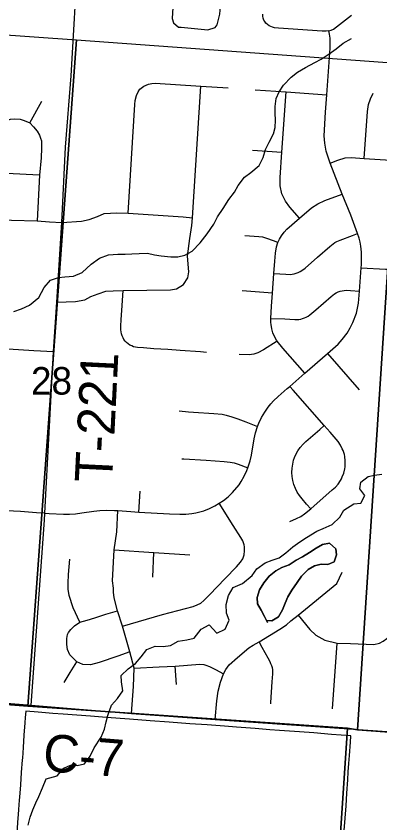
# Model space of a CAD drawing. Extents: x 0 to 34, y 0 to 26.1.
# Drawn here: x 26.1 to 26.652, y 15.919 to 17.147 of the extents above; entities that cross this region are included whole.
import ezdxf

# ---------------------------------------------------------------- set-up
doc = ezdxf.new("R2010")
doc.units = 0
for name, color, linetype in [('GM_X_County_Road', 7, 'Continuous'), ('GM_X_County_Road_Text', 7, 'Continuous'), ('GM_X_Minor_Lake', 7, 'Continuous'), ('GM_X_Minor_River', 7, 'Continuous'), ('GM_X_Section', 7, 'Continuous'), ('GM_X_Section_Text', 7, 'Continuous'), ('GM_X_Township_Road', 7, 'Continuous'), ('GM_X_Township_Road_Text', 7, 'Continuous'), ('SC_Scratch1', 7, 'Continuous')]:
    doc.layers.add(name, color=color, linetype=linetype)

msp = doc.modelspace()

# ---------------------------------------------------------------- linework, layer by layer
at = {"layer": 'GM_X_County_Road'}
msp.add_lwpolyline([(25.6593, 16.1329), (25.6738, 16.1311), (25.7938, 16.1231), (25.9933, 16.107), (26.0793, 16.1018), (26.1222, 16.0984), (26.2747, 16.0857), (26.4019, 16.0766), (26.714, 16.0547), (26.8597, 16.0424), (26.9166, 16.0392), (26.9722, 16.0347), (26.9948, 16.0336), (27.0202, 16.032), (27.0574, 16.0287), (27.1095, 16.024), (27.2972, 16.0095), (27.3012, 16.0092)], dxfattribs=at)
at = {"layer": 'GM_X_Minor_Lake'}
for points in [[(26.4879, 16.2266), (26.4982, 16.233), (26.5043, 16.2433), (26.5081, 16.2536), (26.5123, 16.2635), (26.5187, 16.2734), (26.5264, 16.2852), (26.5332, 16.2947), (26.5431, 16.305), (26.5527, 16.3103), (26.5633, 16.313), (26.5732, 16.3126), (26.5828, 16.3168), (26.5862, 16.3271), (26.5854, 16.3366), (26.5759, 16.345), (26.5652, 16.3431), (26.5557, 16.3374), (26.5454, 16.3309), (26.5348, 16.3244), (26.5252, 16.3191), (26.5142, 16.3118), (26.5035, 16.3077), (26.494, 16.3031), (26.4841, 16.2947), (26.4757, 16.2848), (26.4692, 16.2738), (26.4658, 16.2623), (26.4665, 16.2524), (26.4719, 16.2429), (26.4768, 16.2334), (26.4801, 16.2274)], [(26.4822, 16.2235), (26.4768, 16.2334), (26.4719, 16.2429), (26.4665, 16.2524), (26.4658, 16.2623), (26.4692, 16.2738), (26.4757, 16.2848), (26.4841, 16.2947), (26.494, 16.3031), (26.5035, 16.3077), (26.5142, 16.3118), (26.5252, 16.3191), (26.5348, 16.3244), (26.5454, 16.3309), (26.5557, 16.3374), (26.5652, 16.3431), (26.5759, 16.345), (26.5854, 16.3366), (26.5862, 16.3271), (26.5828, 16.3168), (26.5732, 16.3126), (26.5633, 16.313), (26.5527, 16.3103), (26.5431, 16.305), (26.5332, 16.2947), (26.5264, 16.2852), (26.5187, 16.2734), (26.5123, 16.2635), (26.5081, 16.2536), (26.5043, 16.2433), (26.4982, 16.233), (26.4879, 16.2266), (26.4806, 16.2273)], [(26.4801, 16.2274), (26.4879, 16.2266)]]:
    msp.add_lwpolyline(points, dxfattribs=at)
at = {"layer": 'GM_X_Minor_River'}
for points in [[(26.4312, 16.8791), (26.4367, 16.8893), (26.4467, 16.9021), (26.4563, 16.9088), (26.4689, 16.9196), (26.4751, 16.932), (26.4787, 16.9441), (26.4842, 16.9551), (26.4904, 16.9679), (26.4932, 16.9777), (26.4937, 16.9887), (26.4931, 16.9994), (26.4929, 17.0096), (26.4946, 17.0217), (26.4993, 17.0319), (26.5058, 17.0421), (26.5177, 17.0541), (26.5273, 17.0619), (26.5391, 17.0689), (26.5536, 17.0767), (26.5632, 17.0815), (26.5754, 17.0897), (26.5861, 17.0971), (26.5964, 17.1057), (26.609, 17.1132)], [(26.096, 16.6974), (26.1078, 16.7018), (26.1196, 16.7073), (26.1338, 16.7189), (26.1423, 16.7339), (26.1515, 16.7452), (26.1641, 16.7492), (26.1736, 16.7502), (26.1868, 16.7515), (26.1998, 16.7571), (26.2136, 16.7698), (26.2262, 16.7787), (26.2399, 16.7838), (26.2539, 16.7848), (26.2653, 16.785), (26.2755, 16.7852), (26.2865, 16.7859), (26.299, 16.7864), (26.3099, 16.784), (26.3197, 16.7824), (26.3348, 16.7806), (26.3454, 16.7809), (26.3561, 16.783), (26.3668, 16.7893), (26.379, 16.802), (26.3898, 16.8156), (26.3999, 16.8302), (26.4053, 16.8415), (26.4142, 16.8543), (26.4227, 16.8679), (26.4312, 16.8791)], [(26.1178, 15.916), (26.121, 15.9281), (26.1249, 15.9394), (26.1296, 15.9496), (26.1339, 15.9594), (26.1394, 15.9726), (26.1453, 15.9862), (26.1616, 15.9909), (26.172, 16.0025), (26.1819, 16.0069), (26.1921, 16.0064), (26.2035, 16.0093), (26.212, 16.0206), (26.2182, 16.0334), (26.2287, 16.05), (26.2338, 16.062), (26.2362, 16.073), (26.2386, 16.0828), (26.2445, 16.0983), (26.2534, 16.1084), (26.2615, 16.1205), (26.2598, 16.1342), (26.2592, 16.1437), (26.2699, 16.1538), (26.281, 16.1616), (26.2895, 16.1721), (26.2983, 16.183), (26.3109, 16.1881), (26.323, 16.1879), (26.334, 16.1893), (26.3458, 16.196), (26.3587, 16.1977), (26.3701, 16.2006), (26.3809, 16.2141), (26.3927, 16.2208), (26.4046, 16.2081), (26.4172, 16.2143), (26.4231, 16.2279), (26.4191, 16.2382), (26.4185, 16.2515), (26.4221, 16.2651), (26.4295, 16.2776), (26.4436, 16.2834), (26.4581, 16.2958), (26.4655, 16.3059), (26.4777, 16.3152), (26.4887, 16.3192), (26.499, 16.3229), (26.5093, 16.3304), (26.52, 16.3393), (26.5308, 16.3471), (26.5407, 16.3538), (26.5567, 16.3631), (26.5662, 16.3671), (26.5796, 16.3734), (26.5915, 16.3843), (26.5977, 16.3952), (26.6129, 16.4048), (26.6232, 16.4058), (26.6294, 16.4175), (26.6216, 16.4275), (26.6232, 16.4377), (26.6343, 16.4463), (26.6442, 16.4484), (26.6552, 16.4498)]]:
    msp.add_lwpolyline(points, dxfattribs=at)
at = {"layer": 'GM_X_Section'}
for points in [[(26.1914, 17.1109), (26.1174, 16.097), (25.6194, 16.135), (25.6903, 17.1467)], [(26.6845, 17.0747), (26.6185, 16.0611), (26.603, 16.0634), (26.1174, 16.097), (26.1914, 17.1109)], [(26.6845, 17.0747), (27.1906, 17.0366), (27.1167, 16.0245), (26.6185, 16.0611)], [(25.6194, 16.135), (26.1174, 16.097), (26.603, 16.0634), (26.5367, 15.0651), (25.5463, 15.1393)], [(26.603, 16.0634), (26.6185, 16.0611), (27.1167, 16.0245), (27.6154, 15.9857), (27.5444, 14.9891), (26.5367, 15.0651)]]:
    msp.add_lwpolyline(points, close=True, dxfattribs=at)
at = {"layer": 'GM_X_Township_Road'}
for p, q in [((26.1203, 16.9845), (26.1383, 17.0177)), ((26.4588, 16.9431), (26.5035, 16.9402)), ((26.135, 16.9048), (26.0849, 16.9073)), ((26.1501, 16.8342), (26.1691, 16.8329)), ((26.4891, 16.7253), (26.4431, 16.7288)), ((26.1561, 16.6361), (26.1266, 16.6379)), ((26.5727, 16.6334), (26.621, 16.5781)), ((26.2858, 16.3924), (26.2881, 16.4241)), ((26.3073, 16.293), (26.3087, 16.3308)), ((26.5802, 16.0927), (26.5873, 16.1928)), ((26.3431, 16.1301), (26.3414, 16.158))]:
    msp.add_line(p, q, dxfattribs=at)
for points in [[(26.1222, 16.0984), (26.1425, 16.38), (26.1431, 16.3905), (26.1561, 16.6361), (26.1614, 16.7119), (26.1691, 16.8329), (26.1747, 16.9478), (26.1829, 17.0561), (26.1938, 17.2401), (26.1989, 17.3186), (26.2003, 17.3492), (26.2093, 17.4126), (26.2156, 17.5128), (26.2187, 17.5533), (26.2208, 17.5954), (26.2209, 17.6031), (26.2201, 17.6132)], [(26.3591, 17.2892), (26.3452, 17.2776), (26.3343, 17.2676), (26.33, 17.2604), (26.3272, 17.2551), (26.3258, 17.2493), (26.3249, 17.2443), (26.3244, 17.2374), (26.3275, 17.2263), (26.3362, 17.203), (26.3382, 17.1981), (26.3394, 17.1844), (26.3383, 17.1682), (26.3368, 17.1436), (26.3387, 17.1366), (26.3464, 17.1304), (26.3501, 17.13), (26.3908, 17.1263), (26.4018, 17.1296), (26.4051, 17.1337), (26.4092, 17.1502), (26.419, 17.2723)], [(26.5745, 17.1246), (26.5705, 17.1242), (26.5645, 17.1243), (26.4982, 17.1286), (26.4921, 17.1293), (26.4892, 17.13), (26.4864, 17.131), (26.4838, 17.1324), (26.4814, 17.1342), (26.4792, 17.1362), (26.4774, 17.1386), (26.476, 17.1411), (26.475, 17.1439), (26.4744, 17.1468), (26.4742, 17.1498)], [(26.5745, 17.1246), (26.5785, 17.1258), (26.582, 17.1274), (26.6089, 17.1484)], [(26.1431, 16.3905), (26.1497, 16.3901), (26.1715, 16.3889), (26.1807, 16.3889), (26.1899, 16.3896), (26.1991, 16.3909), (26.2176, 16.3939), (26.2269, 16.3948), (26.2363, 16.3952), (26.2488, 16.3948), (26.254, 16.3945), (26.2736, 16.3931), (26.2858, 16.3924), (26.3326, 16.3896), (26.3481, 16.3889), (26.3574, 16.3891), (26.3666, 16.39), (26.3726, 16.391), (26.3786, 16.3925), (26.3845, 16.3943), (26.3931, 16.3977), (26.4014, 16.4018), (26.4082, 16.4058), (26.4145, 16.41), (26.4217, 16.4157), (26.4284, 16.4221), (26.4383, 16.4339), (26.4417, 16.439), (26.4462, 16.4471), (26.4502, 16.4555), (26.4517, 16.4594), (26.4551, 16.4701), (26.4571, 16.4791), (26.4612, 16.5037), (26.4632, 16.5128), (26.4664, 16.5227), (26.4683, 16.5276), (26.4725, 16.5361), (26.4773, 16.5442), (26.4826, 16.5519), (26.4866, 16.5568), (26.4908, 16.5614), (26.4975, 16.568), (26.5116, 16.5803), (26.5154, 16.5836), (26.5383, 16.6035), (26.5727, 16.6334), (26.5887, 16.6479), (26.595, 16.6547), (26.6024, 16.6646), (26.6072, 16.6725), (26.6113, 16.6808), (26.6166, 16.6952), (26.6196, 16.7103), (26.6214, 16.7286), (26.6238, 16.764), (26.6241, 16.7692), (26.6245, 16.7785), (26.6242, 16.7877), (26.6232, 16.7969), (26.6221, 16.803), (26.6207, 16.809), (26.6183, 16.8164), (26.6079, 16.8439), (26.5952, 16.8763), (26.5768, 16.9233), (26.5708, 16.9416), (26.5686, 16.9538), (26.5675, 16.9647), (26.5696, 17.0007), (26.5715, 17.0274), (26.5766, 17.0982), (26.5769, 17.1074), (26.5767, 17.1136), (26.5762, 17.1166), (26.5755, 17.1196), (26.5745, 17.1246)], [(26.1614, 16.7119), (26.1898, 16.7125), (26.2039, 16.7154), (26.2131, 16.7201), (26.2244, 16.7245), (26.2358, 16.7286), (26.2468, 16.7291), (26.262, 16.7295), (26.3339, 16.7304), (26.3431, 16.732), (26.3536, 16.7386), (26.3602, 16.749), (26.362, 16.7581), (26.3601, 16.7815), (26.3636, 16.8088), (26.3666, 16.8283), (26.3676, 16.8403), (26.3802, 17.0405)], [(26.2849, 17.0318), (26.2875, 17.0357), (26.2935, 17.0406), (26.3007, 17.0436), (26.3058, 17.0446), (26.3109, 17.0448), (26.3802, 17.0405), (26.4218, 17.0377)], [(26.2698, 16.8474), (26.2797, 17.0124), (26.2803, 17.0187), (26.2822, 17.0262), (26.2849, 17.0318)], [(26.4629, 17.0349), (26.5099, 17.0316), (26.5715, 17.0274)], [(26.5303, 16.8396), (26.5156, 16.8563), (26.5088, 16.8656), (26.5034, 16.8767), (26.5007, 16.8889), (26.5006, 16.9013), (26.5035, 16.9402), (26.5099, 17.0316)], [(26.6286, 16.9306), (26.6336, 17.002), (26.6351, 17.0124), (26.638, 17.0213), (26.642, 17.0298)], [(25.9929, 16.9505), (26.068, 16.9813), (26.0824, 16.9875), (26.0908, 16.9902), (26.097, 16.9909), (26.1054, 16.9902), (26.1118, 16.9882), (26.1203, 16.9845), (26.1258, 16.9788), (26.1312, 16.9719), (26.1349, 16.9658), (26.1363, 16.9614), (26.1381, 16.9573), (26.1381, 16.9459), (26.1376, 16.9315), (26.135, 16.9048), (26.1312, 16.8355)], [(26.6238, 16.764), (26.6606, 16.7619), (26.6668, 16.7617), (26.673, 16.7622), (26.6761, 16.7628), (26.682, 16.7648), (26.6874, 16.7679), (26.6898, 16.7699), (26.692, 16.772), (26.694, 16.7744), (26.6958, 16.777), (26.6973, 16.7798), (26.6985, 16.7826), (26.6996, 16.7856), (26.7013, 16.7947), (26.7041, 16.8383), (26.7067, 16.877), (26.71, 16.9252), (26.7125, 16.9642)], [(26.5768, 16.9233), (26.5883, 16.9277), (26.5994, 16.9312), (26.6086, 16.9317), (26.6286, 16.9306), (26.71, 16.9252)], [(26.5383, 16.6035), (26.5048, 16.6415), (26.496, 16.6525), (26.4951, 16.6538), (26.4921, 16.6594), (26.4898, 16.6653), (26.4881, 16.6713), (26.487, 16.6776), (26.4868, 16.6807), (26.4868, 16.687), (26.4878, 16.7057), (26.4891, 16.7253), (26.4912, 16.7552), (26.4924, 16.774), (26.4935, 16.7864), (26.4951, 16.7957), (26.4973, 16.8023), (26.4996, 16.8075), (26.5029, 16.8129), (26.5067, 16.818), (26.5111, 16.8226), (26.5303, 16.8396), (26.5486, 16.8553), (26.5578, 16.8615), (26.5688, 16.8663), (26.5952, 16.8763)], [(26.1691, 16.8329), (26.1986, 16.8351), (26.2106, 16.8377), (26.2232, 16.8421), (26.2332, 16.8468), (26.2526, 16.8478), (26.2698, 16.8474), (26.3535, 16.8418), (26.3676, 16.8403)], [(26.0263, 16.8395), (26.0924, 16.8364), (26.1312, 16.8355), (26.1501, 16.8342)], [(26.4973, 16.8023), (26.4905, 16.805), (26.4806, 16.8088), (26.4746, 16.8104), (26.4685, 16.8114), (26.4468, 16.8128)], [(26.4912, 16.7552), (26.5096, 16.7542), (26.5158, 16.754), (26.5191, 16.7543), (26.5222, 16.7548), (26.5253, 16.7557), (26.5283, 16.7569), (26.5311, 16.7583), (26.5365, 16.7617), (26.5389, 16.7637), (26.5576, 16.7801), (26.5763, 16.7966), (26.5837, 16.8023), (26.587, 16.8043), (26.5917, 16.8063), (26.6105, 16.8134), (26.6183, 16.8164)], [(26.3888, 16.6353), (26.3796, 16.6359), (26.3487, 16.6382), (26.3302, 16.6395), (26.3086, 16.6409), (26.2932, 16.642), (26.284, 16.6428), (26.281, 16.6433), (26.278, 16.644), (26.2751, 16.6451), (26.2723, 16.6465), (26.2697, 16.6482), (26.2674, 16.6502), (26.2652, 16.6524), (26.2634, 16.6549), (26.2619, 16.6576), (26.2608, 16.6605), (26.2598, 16.6634), (26.2592, 16.6664), (26.2587, 16.6695), (26.2586, 16.6726), (26.2586, 16.6757), (26.259, 16.6849), (26.2607, 16.7065), (26.2616, 16.7219), (26.262, 16.7295)], [(26.4868, 16.687), (26.5077, 16.6862), (26.5229, 16.6854), (26.529, 16.6856), (26.532, 16.6861), (26.5349, 16.6868), (26.5377, 16.6878), (26.5405, 16.6891), (26.5431, 16.6906), (26.5456, 16.6923), (26.555, 16.7002), (26.5783, 16.7206), (26.5834, 16.7243), (26.5861, 16.726), (26.589, 16.7273), (26.592, 16.7284), (26.5951, 16.7291), (26.5982, 16.7296), (26.6014, 16.7298), (26.6077, 16.7296), (26.6214, 16.7286)], [(26.1266, 16.6379), (26.0481, 16.6426), (26.0088, 16.647), (25.9979, 16.647), (25.9877, 16.6492), (25.975, 16.6535), (25.9612, 16.6634), (25.935, 16.6898)], [(26.496, 16.6525), (26.4752, 16.6392), (26.4667, 16.6346), (26.4605, 16.6326), (26.4573, 16.632), (26.4541, 16.6317), (26.4385, 16.6319)], [(26.5156, 16.3781), (26.5258, 16.3825), (26.532, 16.3858), (26.5377, 16.3894), (26.5473, 16.3973), (26.58, 16.4259), (26.5846, 16.4302), (26.5887, 16.435), (26.5923, 16.4402), (26.5938, 16.443), (26.5952, 16.4458), (26.5973, 16.4517), (26.5988, 16.4579), (26.5993, 16.461), (26.5996, 16.4641), (26.5996, 16.4704), (26.5989, 16.4767), (26.5983, 16.4798), (26.5974, 16.4828), (26.5964, 16.4858), (26.5952, 16.4887), (26.5923, 16.4943), (26.5887, 16.4995), (26.5766, 16.5138), (26.5678, 16.5238), (26.5206, 16.5777), (26.5154, 16.5836)], [(26.3472, 16.5464), (26.3614, 16.5447), (26.369, 16.5443), (26.4001, 16.5422), (26.4125, 16.5413), (26.4185, 16.54), (26.4274, 16.5373), (26.4362, 16.5342), (26.4484, 16.5296), (26.4664, 16.5227)], [(26.5473, 16.3973), (26.541, 16.4045), (26.534, 16.4126), (26.5302, 16.4175), (26.5267, 16.4227), (26.5239, 16.4283), (26.5216, 16.4341), (26.5199, 16.4402), (26.5189, 16.4464), (26.5185, 16.4527), (26.5188, 16.459), (26.5198, 16.4652), (26.5212, 16.4713), (26.5227, 16.4754), (26.5247, 16.48), (26.5277, 16.4855), (26.5313, 16.4906), (26.5355, 16.4954), (26.54, 16.4996), (26.5611, 16.5178), (26.5678, 16.5238)], [(26.3512, 16.4733), (26.3544, 16.4732), (26.3881, 16.4711), (26.4158, 16.4691), (26.4249, 16.4681), (26.4309, 16.467), (26.4368, 16.4652), (26.4517, 16.4594)], [(26.2611, 16.2186), (26.3219, 16.2364), (26.3686, 16.2488), (26.3745, 16.251), (26.38, 16.2538), (26.3848, 16.2577), (26.3935, 16.2666), (26.4172, 16.2911), (26.4345, 16.3089), (26.4406, 16.3159), (26.4439, 16.3212), (26.4459, 16.3271), (26.4467, 16.3332), (26.4465, 16.3395), (26.4461, 16.3425), (26.4452, 16.3455), (26.444, 16.3483), (26.441, 16.3538), (26.4294, 16.3721), (26.4082, 16.4058)], [(26.1431, 16.3905), (26.1303, 16.391), (26.1059, 16.393), (26.0741, 16.3949)], [(26.2747, 16.0857), (26.2777, 16.1271), (26.279, 16.1549), (26.2725, 16.1797), (26.2611, 16.2186), (26.2535, 16.2419), (26.2486, 16.2617), (26.2476, 16.2704), (26.2472, 16.2763), (26.2461, 16.2876), (26.2486, 16.3347), (26.2523, 16.3622), (26.254, 16.3945)], [(26.2486, 16.3347), (26.3087, 16.3308), (26.3633, 16.3271)], [(26.1965, 16.2245), (26.1864, 16.2464), (26.1801, 16.2655), (26.1785, 16.275), (26.1788, 16.2841), (26.1792, 16.2974), (26.181, 16.3207)], [(26.528, 16.2353), (26.5871, 16.2838), (26.5949, 16.3009)], [(26.2725, 16.1797), (26.2542, 16.1732), (26.2259, 16.1632), (26.2123, 16.1599), (26.201, 16.1604), (26.1916, 16.1644), (26.1855, 16.1703), (26.1812, 16.1752), (26.1775, 16.183), (26.1763, 16.1908), (26.1763, 16.2), (26.1775, 16.2059), (26.1791, 16.2092), (26.1824, 16.2136), (26.1883, 16.2193), (26.1965, 16.2245), (26.2076, 16.2278), (26.2189, 16.2313), (26.2359, 16.2367), (26.2535, 16.2419)], [(26.4019, 16.0766), (26.4044, 16.1049), (26.4065, 16.12), (26.41, 16.1336), (26.4145, 16.1462), (26.418, 16.1528), (26.4231, 16.1599), (26.4358, 16.171), (26.4532, 16.1857), (26.4597, 16.1898), (26.469, 16.1949), (26.5001, 16.214), (26.5102, 16.2207), (26.5171, 16.2268), (26.528, 16.2353)], [(26.528, 16.2353), (26.5458, 16.2137), (26.5551, 16.2052), (26.5687, 16.1973), (26.5873, 16.1928), (26.6077, 16.1922), (26.643, 16.191), (26.6519, 16.1926), (26.6571, 16.1957), (26.6631, 16.1998), (26.674, 16.2087)], [(26.4864, 16.1003), (26.4866, 16.1024), (26.4876, 16.1181), (26.4888, 16.1337), (26.4898, 16.1462), (26.4898, 16.1494), (26.4896, 16.1525), (26.489, 16.1555), (26.488, 16.1585), (26.4868, 16.1614), (26.4855, 16.1643), (26.4826, 16.1699), (26.4736, 16.1864), (26.469, 16.1949)], [(26.1725, 16.1331), (26.1817, 16.1481), (26.1916, 16.1644)], [(26.279, 16.1549), (26.3171, 16.1569), (26.3414, 16.158), (26.3789, 16.1608), (26.3849, 16.1601), (26.3876, 16.1595), (26.3935, 16.1574), (26.4026, 16.1529), (26.4145, 16.1462)]]:
    msp.add_lwpolyline(points, dxfattribs=at)
at = {"layer": 'SC_Scratch1'}
msp.add_lwpolyline([(26.5982, 15.9076), (26.5995, 15.9265), (26.6008, 15.9454), (26.6021, 15.9643), (26.6035, 15.9847), (26.6043, 15.997), (26.6052, 16.0097), (26.606, 16.0216), (26.6074, 16.0419), (26.6081, 16.0519), (26.5788, 16.054), (26.5518, 16.0561), (26.5301, 16.0577), (26.515, 16.0588), (26.4999, 16.06), (26.4848, 16.0611), (26.4626, 16.0628), (26.4346, 16.0649), (26.4163, 16.0663), (26.3899, 16.0683), (26.3634, 16.0702), (26.3321, 16.0726), (26.303, 16.0748), (26.2718, 16.0771), (26.2369, 16.0797), (26.2123, 16.0816), (26.1916, 16.0833), (26.1708, 16.0849), (26.1555, 16.086), (26.1328, 16.0877), (26.1141, 16.0891), (26.1134, 16.0797), (26.1128, 16.0717), (26.1114, 16.0529), (26.1101, 16.034), (26.1089, 16.0177), (26.1087, 16.0151), (26.1073, 15.9962), (26.1059, 15.9773), (26.1045, 15.9584), (26.1042, 15.9539), (26.1031, 15.9395), (26.1025, 15.932), (26.1017, 15.9206), (26.1003, 15.9018)], dxfattribs=at)

# ---------------------------------------------------------------- texts
at = {"layer": 'GM_X_County_Road_Text'}
msp.add_text('C-7', height=0.05682, rotation=355.4251, dxfattribs=at).set_placement((26.1388, 15.9985))
at = {"layer": 'GM_X_Section_Text'}
msp.add_text('28', height=0.04186, rotation=0, dxfattribs=at).set_placement((26.1221, 16.5711))
at = {"layer": 'GM_X_Township_Road_Text'}
msp.add_text('T-221', height=0.05682, rotation=87.1941, dxfattribs=at).set_placement((26.2452, 16.4362))

doc.saveas('drawing.dxf')
